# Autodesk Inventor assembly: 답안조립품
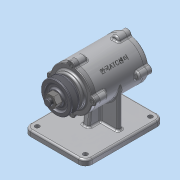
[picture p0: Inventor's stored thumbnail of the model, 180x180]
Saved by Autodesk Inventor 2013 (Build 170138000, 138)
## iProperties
Created: 2015-12
Part Number: 답안조립품
Document SubType Name: Assembly
Designer: ST1
Author: ST1
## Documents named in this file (11)
- C:\Users\ST1\Desktop\451207V1013\답안조립품.iam
- C:\Users\ST1\Desktop\451207V1013\1-본체.ipt
- C:\Users\ST1\Desktop\451207V1013\커버.ipt
- C:\Users\ST1\Desktop\451207V1013\커버2.ipt
- C:\Users\ST1\Desktop\451207V1013\축.ipt
- C:\Users\ST1\Desktop\451207V1013\키(4 x 4 x 12).ipt
- C:\Users\ST1\Desktop\451207V1013\베어링 6204.ipt
- C:\Users\ST1\Desktop\451207V1013\오일실.ipt
- C:\Users\ST1\Desktop\451207V1013\볼트 M4 x 12.ipt
- C:\Users\ST1\Desktop\451207V1013\V-벨트풀리.ipt
- C:\Users\ST1\Desktop\451207V1013\너트 M12x1.25.ipt
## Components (7 placed, 6 different names)
1. 1-본체:1 — 각도:2
2. KS B 1311 (I) 4 x 4 x 12:1 — 각도:1, 각도:2, 각도:3
3. KS B 2023 6204 - 20 x 47 x 14:1
4. KS B 2023 6204 - 20 x 47 x 14:2
5. KS B 2804 D D - 20 32 8:1 — 플러쉬:1
6. V-벨트풀리:1 — 각도:3, 각도:4
7. KS B 1012 클래스 1 일반 - 미터 M12x1.25:1 — 각도:4
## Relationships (5: Angle 4, Flush 1)
- 각도:1 [Angle]: KS B 1311 (I) 4 x 4 x 12:1
- 각도:2 [Angle]: 1-본체:1 ↔ KS B 1311 (I) 4 x 4 x 12:1
- 플러쉬:1 [Flush]: KS B 2804 D D - 20 32 8:1
- 각도:3 [Angle]: KS B 1311 (I) 4 x 4 x 12:1 ↔ V-벨트풀리:1
- 각도:4 [Angle]: V-벨트풀리:1 ↔ KS B 1012 클래스 1 일반 - 미터 M12x1.25:1
